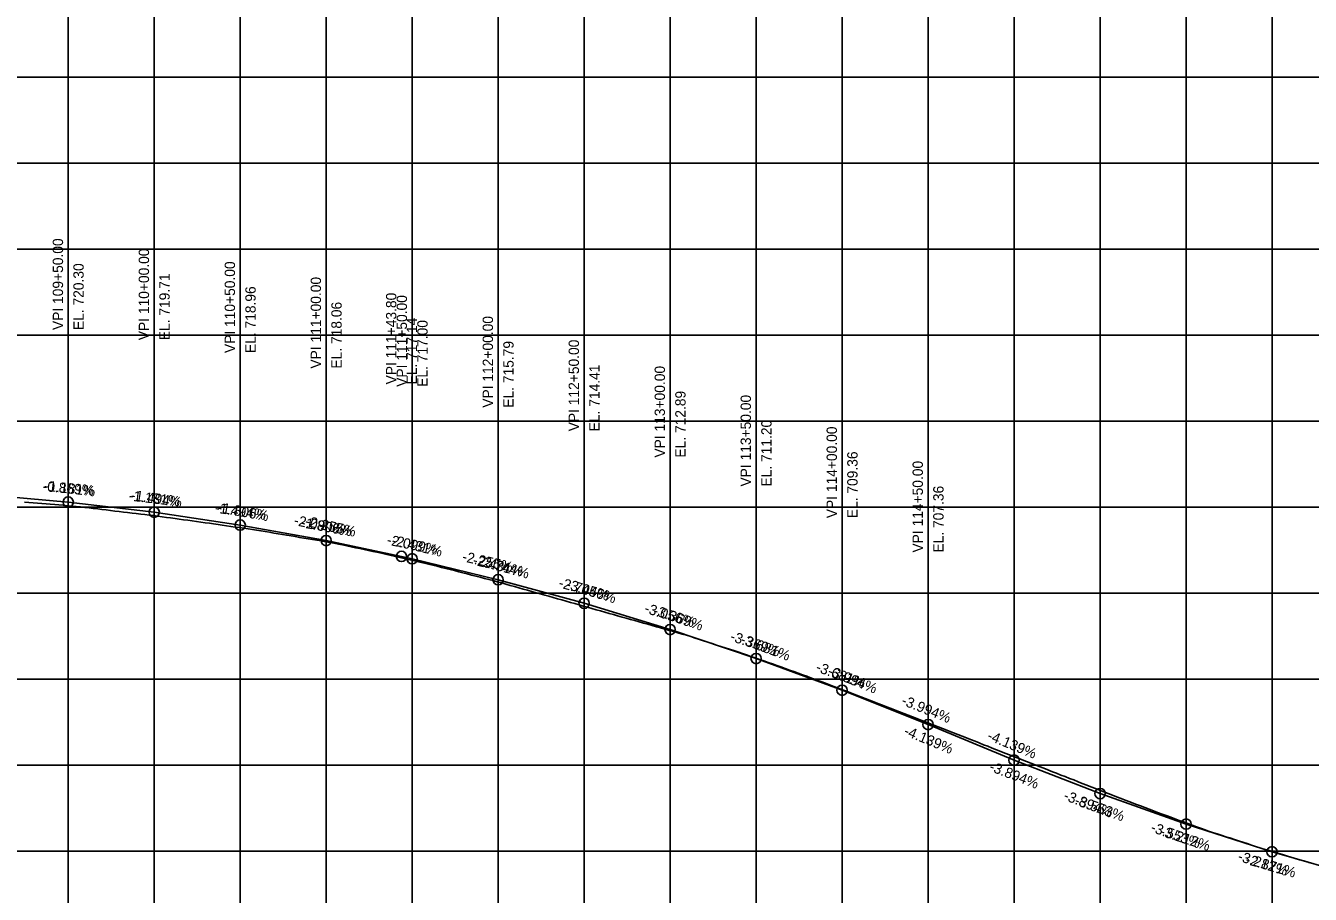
# Model space of a CAD drawing. Extents: x -7164 to 2214450, y -19642 to 253469.
# Drawn here: x 18125 to 18872, y -2525 to -2020 of the extents above; entities that cross this region are included whole.
import ezdxf

# ---------------------------------------------------------------- set-up
doc = ezdxf.new("R2010")
doc.units = 0
for name, color, linetype in [('DESIGN - PROFILE - Proposed', 7, 'Continuous'), ('DESIGN - PROFILE - Proposed Curve Text', 7, 'Continuous'), ('DESIGN - PROFILE - Proposed Text', 7, 'Continuous'), ('DESIGN - SHEET - Light Grid', 7, 'Continuous'), ('SURVEY - PROFILE - Ground Line with Text', 7, 'Continuous')]:
    doc.layers.add(name, color=color, linetype=linetype)

msp = doc.modelspace()

# ---------------------------------------------------------------- linework, layer by layer
at = {"layer": 'DESIGN - PROFILE - Proposed'}
msp.add_lwpolyline([(18100, -2292.64), (18150, -2296.98), (18200, -2302.89), (18250, -2310.36), (18300, -2319.39), (18343.8, -2328.59), (18350, -2329.98), (18400, -2342.14), (18450, -2355.86), (18500, -2371.14), (18550, -2387.98), (18600, -2406.39), (18650, -2426.36), (18700, -2447.06), (18750, -2466.53), (18800, -2484.29), (18850, -2500.35), (18900, -2514.7)], dxfattribs=at)
msp.add_lwpolyline([(18100, -2292.64), (18150, -2296.98), (18200, -2302.89), (18250, -2310.36), (18300, -2319.39), (18343.8, -2328.59), (18350, -2329.98), (18400, -2342.14), (18450, -2355.86), (18500, -2371.14), (18550, -2387.98), (18600, -2406.39), (18650, -2426.36), (18700, -2447.06), (18750, -2466.53), (18800, -2484.29), (18850, -2500.35), (18900, -2514.7)], dxfattribs=at)
at = {"layer": 'DESIGN - PROFILE - Proposed Text'}
for centre in [(18150, -2296.98), (18150, -2296.98), (18200, -2302.89), (18200, -2302.89), (18250, -2310.36), (18250, -2310.36), (18300, -2319.39), (18300, -2319.39), (18343.8, -2328.59), (18343.8, -2328.59), (18350, -2329.98), (18350, -2329.98), (18400, -2342.14), (18400, -2342.14), (18450, -2355.86), (18450, -2355.86), (18500, -2371.14), (18500, -2371.14), (18550, -2387.98), (18550, -2387.98), (18600, -2406.39), (18600, -2406.39), (18650, -2426.36), (18650, -2426.36), (18700, -2447.06), (18700, -2447.06), (18750, -2466.53), (18750, -2466.53), (18800, -2484.29), (18800, -2484.29), (18850, -2500.35), (18850, -2500.35)]:
    msp.add_circle(centre, 3, dxfattribs=at)
at = {"layer": 'DESIGN - SHEET - Light Grid'}
for p, q in [((18150, -3000), (18150, -1000)), ((18150, -3000), (18150, -1000)), ((18200, -3000), (18200, -1000)), ((18200, -3000), (18200, -1000)), ((18250, -3000), (18250, -1000)), ((18250, -3000), (18250, -1000)), ((18300, -3000), (18300, -1000)), ((18300, -3000), (18300, -1000)), ((18350, -3000), (18350, -1000)), ((18350, -3000), (18350, -1000)), ((18400, -3000), (18400, -1000)), ((18400, -3000), (18400, -1000)), ((18450, -3000), (18450, -1000)), ((18450, -3000), (18450, -1000)), ((18500, -3000), (18500, -1000)), ((18500, -3000), (18500, -1000)), ((18550, -3000), (18550, -1000)), ((18550, -3000), (18550, -1000)), ((18600, -3000), (18600, -1000)), ((18600, -3000), (18600, -1000)), ((18650, -3000), (18650, -1000)), ((18650, -3000), (18650, -1000)), ((18700, -3000), (18700, -1000)), ((18700, -3000), (18700, -1000)), ((18750, -3000), (18750, -1000)), ((18750, -3000), (18750, -1000)), ((18800, -3000), (18800, -1000)), ((18800, -3000), (18800, -1000)), ((18850, -3000), (18850, -1000)), ((18850, -3000), (18850, -1000)), ((15000, -2050), (24100, -2050)), ((15000, -2050), (24100, -2050)), ((15000, -2100), (24100, -2100)), ((15000, -2100), (24100, -2100)), ((15000, -2150), (24100, -2150)), ((15000, -2150), (24100, -2150)), ((15000, -2200), (24100, -2200)), ((15000, -2200), (24100, -2200)), ((15000, -2250), (24100, -2250)), ((15000, -2250), (24100, -2250)), ((15000, -2300), (24100, -2300)), ((15000, -2300), (24100, -2300)), ((15000, -2350), (24100, -2350)), ((15000, -2350), (24100, -2350)), ((15000, -2400), (24100, -2400)), ((15000, -2400), (24100, -2400)), ((15000, -2450), (24100, -2450)), ((15000, -2450), (24100, -2450)), ((15000, -2500), (24100, -2500)), ((15000, -2500), (24100, -2500))]:
    msp.add_line(p, q, dxfattribs=at)
at = {"layer": 'SURVEY - PROFILE - Ground Line with Text'}
for points in [[(18124.57, -2297), (18127.15, -2297.21), (18129.57, -2297.42), (18132.15, -2297.63), (18134.57, -2297.84), (18137.14, -2298.05), (18139.57, -2298.26), (18142.14, -2298.47), (18144.57, -2298.68), (18147.14, -2298.89), (18149.57, -2299.1), (18152.14, -2299.31), (18154.57, -2299.61), (18157.14, -2299.81), (18159.57, -2300.11), (18162.14, -2300.41), (18164.57, -2300.71), (18167.14, -2301.01), (18169.57, -2301.3), (18172.14, -2301.6), (18174.57, -2301.9), (18177.14, -2302.2), (18179.57, -2302.5), (18182.14, -2302.8), (18184.57, -2303.09), (18187.14, -2303.39), (18189.57, -2303.69), (18192.14, -2303.99), (18194.57, -2304.29), (18197.13, -2304.59), (18199.57, -2304.88), (18202.13, -2305.25), (18204.57, -2305.55), (18207.13, -2305.92), (18209.57, -2306.21), (18212.13, -2306.58), (18214.57, -2306.88), (18217.13, -2307.25), (18219.57, -2307.54), (18222.13, -2307.91), (18224.57, -2308.26), (18227.13, -2308.63), (18229.57, -2308.99), (18232.12, -2309.35), (18234.57, -2309.71), (18237.12, -2310.07), (18239.57, -2310.43), (18242.12, -2310.79), (18244.57, -2311.15), (18247.12, -2311.51), (18249.57, -2311.87), (18252.12, -2312.23), (18254.57, -2312.59), (18257.11, -2312.95), (18259.57, -2313.31), (18262.11, -2313.75), (18264.56, -2314.15), (18267.11, -2314.59), (18269.56, -2315), (18272.11, -2315.43), (18274.56, -2315.84), (18277.11, -2316.27), (18279.56, -2316.68), (18282.11, -2317.12), (18284.56, -2317.52)], [(18124.57, -2297), (18127.15, -2297.21), (18129.57, -2297.42), (18132.15, -2297.63), (18134.57, -2297.84), (18137.14, -2298.05), (18139.57, -2298.26), (18142.14, -2298.47), (18144.57, -2298.68), (18147.14, -2298.89), (18149.57, -2299.1), (18152.14, -2299.31), (18154.57, -2299.61), (18157.14, -2299.81), (18159.57, -2300.11), (18162.14, -2300.41), (18164.57, -2300.71), (18167.14, -2301.01), (18169.57, -2301.3), (18172.14, -2301.6), (18174.57, -2301.9), (18177.14, -2302.2), (18179.57, -2302.5), (18182.14, -2302.8), (18184.57, -2303.09), (18187.14, -2303.39), (18189.57, -2303.69), (18192.14, -2303.99), (18194.57, -2304.29), (18197.13, -2304.59), (18199.57, -2304.88), (18202.13, -2305.25), (18204.57, -2305.55), (18207.13, -2305.92), (18209.57, -2306.21), (18212.13, -2306.58), (18214.57, -2306.88), (18217.13, -2307.25), (18219.57, -2307.54), (18222.13, -2307.91), (18224.57, -2308.26), (18227.13, -2308.63), (18229.57, -2308.99), (18232.12, -2309.35), (18234.57, -2309.71), (18237.12, -2310.07), (18239.57, -2310.43), (18242.12, -2310.79), (18244.57, -2311.15), (18247.12, -2311.51), (18249.57, -2311.87), (18252.12, -2312.23), (18254.57, -2312.59), (18257.11, -2312.95), (18259.57, -2313.31), (18262.11, -2313.75), (18264.56, -2314.15), (18267.11, -2314.59), (18269.56, -2315), (18272.11, -2315.43), (18274.56, -2315.84), (18277.11, -2316.27), (18279.56, -2316.68), (18282.11, -2317.12), (18284.56, -2317.52)], [(18284.56, -2317.52), (18287.11, -2317.96), (18289.56, -2318.37), (18292.11, -2318.8), (18294.56, -2319.21), (18297.11, -2319.64), (18299.56, -2320.05), (18302.11, -2320.49), (18304.56, -2320.98), (18307.11, -2321.41), (18309.56, -2321.9), (18312.11, -2322.48), (18314.55, -2322.97), (18317.11, -2323.55), (18319.55, -2324.04), (18322.1, -2324.61), (18324.55, -2325.1), (18327.1, -2325.68), (18329.55, -2326.17), (18332.1, -2326.75), (18334.55, -2327.31), (18337.1, -2327.89), (18339.55, -2328.46), (18342.1, -2329.03), (18344.55, -2329.6), (18347.09, -2330.17), (18349.55, -2330.74), (18352.09, -2331.32), (18354.55, -2331.88), (18357.09, -2332.46), (18359.54, -2333.03), (18362.09, -2333.68), (18364.54, -2334.31), (18367.08, -2334.97), (18369.54, -2335.6), (18372.08, -2336.25), (18374.54, -2336.89), (18377.08, -2337.54), (18379.54, -2338.17), (18382.08, -2338.83), (18384.54, -2339.46), (18387.08, -2340.11), (18389.53, -2340.75), (18392.07, -2341.4), (18394.53, -2342.03), (18397.07, -2342.69), (18399.53, -2343.32), (18402.07, -2344.04), (18404.53, -2344.74), (18407.06, -2345.45), (18409.53, -2346.15), (18412.06, -2346.86), (18414.52, -2347.57), (18417.06, -2348.28), (18419.52, -2348.98), (18422.06, -2349.69), (18424.52, -2350.39), (18427.06, -2351.11), (18429.52, -2351.81), (18432.05, -2352.52), (18434.52, -2353.22), (18437.05, -2353.94), (18439.51, -2354.64), (18442.05, -2355.35), (18444.51, -2356.05), (18447.05, -2356.77), (18449.51, -2357.47), (18452.04, -2358.18), (18454.51, -2358.88), (18457.04, -2359.6), (18459.51, -2360.3), (18462.04, -2361.01), (18464.5, -2361.71), (18467.04, -2362.43), (18469.5, -2363.13), (18472.04, -2363.84), (18474.5, -2364.54), (18477.03, -2365.26), (18479.5, -2365.96), (18482.03, -2366.67), (18484.5, -2367.37), (18487.03, -2368.09), (18489.49, -2368.79), (18492.03, -2369.5), (18494.49, -2370.2), (18497.03, -2370.91), (18499.49, -2371.62), (18502.02, -2372.33), (18504.49, -2373.03), (18507.02, -2373.74), (18509.49, -2374.45), (18512.02, -2375.26), (18514.48, -2376.07), (18517.02, -2376.88), (18519.48, -2377.69), (18522.02, -2378.5), (18524.48, -2379.31), (18527.02, -2380.13), (18529.47, -2380.94), (18532.02, -2381.75), (18534.47, -2382.56)], [(18284.56, -2317.52), (18287.11, -2317.96), (18289.56, -2318.37), (18292.11, -2318.8), (18294.56, -2319.21), (18297.11, -2319.64), (18299.56, -2320.05), (18302.11, -2320.49), (18304.56, -2320.98), (18307.11, -2321.41), (18309.56, -2321.9), (18312.11, -2322.48), (18314.55, -2322.97), (18317.11, -2323.55), (18319.55, -2324.04), (18322.1, -2324.61), (18324.55, -2325.1), (18327.1, -2325.68), (18329.55, -2326.17), (18332.1, -2326.75), (18334.55, -2327.31), (18337.1, -2327.89), (18339.55, -2328.46), (18342.1, -2329.03), (18344.55, -2329.6), (18347.09, -2330.17), (18349.55, -2330.74), (18352.09, -2331.32), (18354.55, -2331.88), (18357.09, -2332.46), (18359.54, -2333.03), (18362.09, -2333.68), (18364.54, -2334.31), (18367.08, -2334.97), (18369.54, -2335.6), (18372.08, -2336.25), (18374.54, -2336.89), (18377.08, -2337.54), (18379.54, -2338.17), (18382.08, -2338.83), (18384.54, -2339.46), (18387.08, -2340.11), (18389.53, -2340.75), (18392.07, -2341.4), (18394.53, -2342.03), (18397.07, -2342.69), (18399.53, -2343.32), (18402.07, -2344.04), (18404.53, -2344.74), (18407.06, -2345.45), (18409.53, -2346.15), (18412.06, -2346.86), (18414.52, -2347.57), (18417.06, -2348.28), (18419.52, -2348.98), (18422.06, -2349.69), (18424.52, -2350.39), (18427.06, -2351.11), (18429.52, -2351.81), (18432.05, -2352.52), (18434.52, -2353.22), (18437.05, -2353.94), (18439.51, -2354.64), (18442.05, -2355.35), (18444.51, -2356.05), (18447.05, -2356.77), (18449.51, -2357.47), (18452.04, -2358.18), (18454.51, -2358.88), (18457.04, -2359.6), (18459.51, -2360.3), (18462.04, -2361.01), (18464.5, -2361.71), (18467.04, -2362.43), (18469.5, -2363.13), (18472.04, -2363.84), (18474.5, -2364.54), (18477.03, -2365.26), (18479.5, -2365.96), (18482.03, -2366.67), (18484.5, -2367.37), (18487.03, -2368.09), (18489.49, -2368.79), (18492.03, -2369.5), (18494.49, -2370.2), (18497.03, -2370.91), (18499.49, -2371.62), (18502.02, -2372.33), (18504.49, -2373.03), (18507.02, -2373.74), (18509.49, -2374.45), (18512.02, -2375.26), (18514.48, -2376.07), (18517.02, -2376.88), (18519.48, -2377.69), (18522.02, -2378.5), (18524.48, -2379.31), (18527.02, -2380.13), (18529.47, -2380.94), (18532.02, -2381.75), (18534.47, -2382.56)], [(18534.47, -2382.56), (18537.02, -2383.37), (18539.47, -2384.18), (18542.01, -2385.1), (18544.46, -2385.91), (18547.01, -2386.82), (18549.46, -2387.63), (18552.01, -2388.55), (18554.46, -2389.36), (18557.01, -2390.28), (18559.45, -2391.08), (18562.01, -2392), (18564.45, -2392.89), (18567, -2393.81), (18569.45, -2394.7), (18572, -2395.62), (18574.44, -2396.51), (18577, -2397.44), (18579.44, -2398.32), (18580.31, -2398.66), (18582.74, -2399.54), (18585.3, -2400.52), (18587.74, -2401.41), (18590.3, -2402.39), (18592.73, -2403.27), (18595.3, -2404.26), (18597.72, -2405.14), (18600.29, -2406.12), (18600.89, -2406.36), (18603.46, -2407.35), (18605.89, -2408.3), (18608.46, -2409.29), (18610.88, -2410.24), (18613.46, -2411.23), (18613.52, -2411.25), (18615.88, -2412.18), (18618.46, -2413.17), (18620.87, -2414.12), (18623.46, -2415.11), (18625.87, -2416.07), (18628.46, -2417.06), (18630.87, -2418.01), (18633.45, -2419), (18635.86, -2419.95), (18638.45, -2420.94), (18640.86, -2421.89), (18643.45, -2422.88), (18645.85, -2423.83), (18648.45, -2424.82), (18650.85, -2425.77), (18653.45, -2426.76), (18655.85, -2427.71), (18658.45, -2428.71), (18660.84, -2429.65), (18662.35, -2430.24), (18664.74, -2431.18), (18667.34, -2432.2), (18669.74, -2433.14), (18672.34, -2434.16), (18674.73, -2435.11), (18677.34, -2436.12), (18679.73, -2437.07), (18682.33, -2438.09), (18684.72, -2439.03), (18687.33, -2440.05), (18689.72, -2440.99), (18692.33, -2442.01), (18694.71, -2442.95), (18697.32, -2443.97), (18699.71, -2444.91), (18702.32, -2445.93), (18704.7, -2446.87), (18707.32, -2447.89), (18709.7, -2448.83), (18712.31, -2449.86), (18714.69, -2450.8), (18717.31, -2451.82), (18719.69, -2452.76), (18722.31, -2453.78), (18724.69, -2454.71), (18727.3, -2455.73), (18729.68, -2456.66), (18732.3, -2457.68), (18734.68, -2458.61), (18737.29, -2459.63), (18739.68, -2460.56), (18742.29, -2461.58), (18744.67, -2462.51), (18747.29, -2463.53), (18749.67, -2464.46), (18752.28, -2465.48), (18754.67, -2466.41), (18757.28, -2467.43), (18759.66, -2468.36), (18762.27, -2469.37), (18764.66, -2470.31), (18767.27, -2471.32), (18769.66, -2472.25), (18771.12, -2472.8), (18773.51, -2473.73), (18776.12, -2474.7)], [(18534.47, -2382.56), (18537.02, -2383.37), (18539.47, -2384.18), (18542.01, -2385.1), (18544.46, -2385.91), (18547.01, -2386.82), (18549.46, -2387.63), (18552.01, -2388.55), (18554.46, -2389.36), (18557.01, -2390.28), (18559.45, -2391.08), (18562.01, -2392), (18564.45, -2392.89), (18567, -2393.81), (18569.45, -2394.7), (18572, -2395.62), (18574.44, -2396.51), (18577, -2397.44), (18579.44, -2398.32), (18580.31, -2398.66), (18582.74, -2399.54), (18585.3, -2400.52), (18587.74, -2401.41), (18590.3, -2402.39), (18592.73, -2403.27), (18595.3, -2404.26), (18597.72, -2405.14), (18600.29, -2406.12), (18600.89, -2406.36), (18603.46, -2407.35), (18605.89, -2408.3), (18608.46, -2409.29), (18610.88, -2410.24), (18613.46, -2411.23), (18613.52, -2411.25), (18615.88, -2412.18), (18618.46, -2413.17), (18620.87, -2414.12), (18623.46, -2415.11), (18625.87, -2416.07), (18628.46, -2417.06), (18630.87, -2418.01), (18633.45, -2419), (18635.86, -2419.95), (18638.45, -2420.94), (18640.86, -2421.89), (18643.45, -2422.88), (18645.85, -2423.83), (18648.45, -2424.82), (18650.85, -2425.77), (18653.45, -2426.76), (18655.85, -2427.71), (18658.45, -2428.71), (18660.84, -2429.65), (18662.35, -2430.24), (18664.74, -2431.18), (18667.34, -2432.2), (18669.74, -2433.14), (18672.34, -2434.16), (18674.73, -2435.11), (18677.34, -2436.12), (18679.73, -2437.07), (18682.33, -2438.09), (18684.72, -2439.03), (18687.33, -2440.05), (18689.72, -2440.99), (18692.33, -2442.01), (18694.71, -2442.95), (18697.32, -2443.97), (18699.71, -2444.91), (18702.32, -2445.93), (18704.7, -2446.87), (18707.32, -2447.89), (18709.7, -2448.83), (18712.31, -2449.86), (18714.69, -2450.8), (18717.31, -2451.82), (18719.69, -2452.76), (18722.31, -2453.78), (18724.69, -2454.71), (18727.3, -2455.73), (18729.68, -2456.66), (18732.3, -2457.68), (18734.68, -2458.61), (18737.29, -2459.63), (18739.68, -2460.56), (18742.29, -2461.58), (18744.67, -2462.51), (18747.29, -2463.53), (18749.67, -2464.46), (18752.28, -2465.48), (18754.67, -2466.41), (18757.28, -2467.43), (18759.66, -2468.36), (18762.27, -2469.37), (18764.66, -2470.31), (18767.27, -2471.32), (18769.66, -2472.25), (18771.12, -2472.8), (18773.51, -2473.73), (18776.12, -2474.7)], [(18776.12, -2474.7), (18778.51, -2475.64), (18781.11, -2476.61), (18783.5, -2477.47), (18786.11, -2478.45), (18788.5, -2479.31), (18791.11, -2480.29), (18793.49, -2481.15), (18796.1, -2482.12), (18798.49, -2482.99), (18801.1, -2483.96), (18803.48, -2484.83), (18806.1, -2485.8), (18808.48, -2486.66), (18811.09, -2487.64), (18813.1, -2488.31), (18815.49, -2489.07), (18818.1, -2489.94), (18820.48, -2490.7), (18823.1, -2491.58), (18825.48, -2492.34), (18828.1, -2493.21), (18830.48, -2493.97), (18833.1, -2494.84), (18835.47, -2495.6), (18838.09, -2496.48), (18840.47, -2497.23), (18841.05, -2497.4), (18843.42, -2498.16), (18846.05, -2498.94), (18848.42, -2499.7), (18851.04, -2500.48), (18853.42, -2501.23), (18856.04, -2502.01), (18858.41, -2502.77), (18861.04, -2503.55), (18863.42, -2504.22), (18866.04, -2505.01), (18868.42, -2505.68), (18871.03, -2506.46), (18871.22, -2506.51), (18873.6, -2507.19)], [(18776.12, -2474.7), (18778.51, -2475.64), (18781.11, -2476.61), (18783.5, -2477.47), (18786.11, -2478.45), (18788.5, -2479.31), (18791.11, -2480.29), (18793.49, -2481.15), (18796.1, -2482.12), (18798.49, -2482.99), (18801.1, -2483.96), (18803.48, -2484.83), (18806.1, -2485.8), (18808.48, -2486.66), (18811.09, -2487.64), (18813.1, -2488.31), (18815.49, -2489.07), (18818.1, -2489.94), (18820.48, -2490.7), (18823.1, -2491.58), (18825.48, -2492.34), (18828.1, -2493.21), (18830.48, -2493.97), (18833.1, -2494.84), (18835.47, -2495.6), (18838.09, -2496.48), (18840.47, -2497.23), (18841.05, -2497.4), (18843.42, -2498.16), (18846.05, -2498.94), (18848.42, -2499.7), (18851.04, -2500.48), (18853.42, -2501.23), (18856.04, -2502.01), (18858.41, -2502.77), (18861.04, -2503.55), (18863.42, -2504.22), (18866.04, -2505.01), (18868.42, -2505.68), (18871.03, -2506.46), (18871.22, -2506.51), (18873.6, -2507.19)]]:
    msp.add_lwpolyline(points, dxfattribs=at)

# ---------------------------------------------------------------- texts
at = {"layer": 'DESIGN - PROFILE - Proposed Curve Text'}
for s, p in [('VPI 109+50.00', (18147, -2196.98)), ('VPI 109+50.00', (18147, -2196.98)), ('VPI 110+00.00', (18197, -2202.89)), ('VPI 110+00.00', (18197, -2202.89)), ('EL. 720.30', (18159, -2196.98)), ('EL. 720.30', (18159, -2196.98)), ('VPI 110+50.00', (18247, -2210.36)), ('VPI 110+50.00', (18247, -2210.36)), ('EL. 719.71', (18209, -2202.89)), ('EL. 719.71', (18209, -2202.89)), ('EL. 718.96', (18259, -2210.36)), ('EL. 718.96', (18259, -2210.36)), ('VPI 111+00.00', (18297, -2219.39)), ('VPI 111+00.00', (18297, -2219.39)), ('EL. 718.06', (18309, -2219.39)), ('EL. 718.06', (18309, -2219.39)), ('VPI 111+43.80', (18340.8, -2228.59)), ('VPI 111+43.80', (18340.8, -2228.59)), ('VPI 111+50.00', (18347, -2229.98)), ('VPI 111+50.00', (18347, -2229.98)), ('EL. 717.14', (18352.8, -2228.59)), ('EL. 717.14', (18352.8, -2228.59)), ('EL. 717.00', (18359, -2229.98)), ('EL. 717.00', (18359, -2229.98)), ('VPI 112+00.00', (18397, -2242.14)), ('VPI 112+00.00', (18397, -2242.14)), ('VPI 112+50.00', (18447, -2255.86)), ('VPI 112+50.00', (18447, -2255.86)), ('EL. 715.79', (18409, -2242.14)), ('EL. 715.79', (18409, -2242.14)), ('EL. 714.41', (18459, -2255.86)), ('EL. 714.41', (18459, -2255.86)), ('VPI 113+00.00', (18497, -2271.14)), ('VPI 113+00.00', (18497, -2271.14)), ('EL. 712.89', (18509, -2271.14)), ('EL. 712.89', (18509, -2271.14)), ('VPI 113+50.00', (18547, -2287.98)), ('VPI 113+50.00', (18547, -2287.98)), ('EL. 711.20', (18559, -2287.98)), ('EL. 711.20', (18559, -2287.98)), ('VPI 114+00.00', (18597, -2306.39)), ('VPI 114+00.00', (18597, -2306.39)), ('EL. 709.36', (18609, -2306.39)), ('EL. 709.36', (18609, -2306.39)), ('VPI 114+50.00', (18647, -2326.36)), ('VPI 114+50.00', (18647, -2326.36)), ('EL. 707.36', (18659, -2326.36)), ('EL. 707.36', (18659, -2326.36))]:
    msp.add_text(s, height=6, rotation=90, dxfattribs=at).set_placement(p)
at = {"layer": 'DESIGN - PROFILE - Proposed Text'}
for s, rotation, p in [('-0.869%', 355.03575, (18134.96, -2290.66)), ('-0.869%', 355.03575, (18134.96, -2290.66)), ('-1.181%', 353.26231, (18135.7, -2290.26)), ('-1.181%', 353.26231, (18135.7, -2290.26)), ('-1.181%', 353.26231, (18185.01, -2296.08)), ('-1.181%', 353.26231, (18185.01, -2296.08)), ('-1.494%', 351.5051, (18186.11, -2295.76)), ('-1.494%', 351.5051, (18186.11, -2295.76)), ('-1.494%', 351.5051, (18235.02, -2303.07)), ('-1.494%', 351.5051, (18235.02, -2303.07)), ('-1.806%', 349.76051, (18236.59, -2302.85)), ('-1.806%', 349.76051, (18236.59, -2302.85)), ('-2.099%', 348.14398, (18280.88, -2310.27)), ('-2.099%', 348.14398, (18280.88, -2310.27)), ('-1.806%', 349.76051, (18285, -2311.6)), ('-1.806%', 349.76051, (18285, -2311.6)), ('-2.255%', 347.29323, (18287.36, -2310.73)), ('-2.255%', 347.29323, (18287.36, -2310.73)), ('-2.099%', 348.14398, (18334.95, -2321.62)), ('-2.099%', 348.14398, (18334.95, -2321.62)), ('-2.431%', 346.33428, (18337.69, -2321.84)), ('-2.431%', 346.33428, (18337.69, -2321.84)), ('-2.255%', 347.29323, (18378.71, -2331.33)), ('-2.255%', 347.29323, (18378.71, -2331.33)), ('-2.431%', 346.33428, (18384.86, -2333.31)), ('-2.431%', 346.33428, (18384.86, -2333.31)), ('-2.744%', 344.65785, (18388.31, -2333.75)), ('-2.744%', 344.65785, (18388.31, -2333.75)), ('-2.744%', 344.65785, (18434.75, -2346.49)), ('-2.744%', 344.65785, (18434.75, -2346.49)), ('-3.056%', 343.00475, (18438.97, -2347.26)), ('-3.056%', 343.00475, (18438.97, -2347.26)), ('-3.056%', 343.00475, (18484.61, -2361.21)), ('-3.056%', 343.00475, (18484.61, -2361.21)), ('-3.369%', 341.38339, (18489.67, -2362.39)), ('-3.369%', 341.38339, (18489.67, -2362.39)), ('-3.369%', 341.38339, (18534.44, -2377.47)), ('-3.369%', 341.38339, (18534.44, -2377.47)), ('-3.681%', 339.78932, (18540.41, -2379.12)), ('-3.681%', 339.78932, (18540.41, -2379.12)), ('-3.681%', 339.78932, (18584.25, -2395.26)), ('-3.681%', 339.78932, (18584.25, -2395.26)), ('-3.994%', 338.23021, (18591.17, -2397.48)), ('-3.994%', 338.23021, (18591.17, -2397.48)), ('-3.994%', 338.23021, (18634.04, -2414.6)), ('-3.994%', 338.23021, (18634.04, -2414.6)), ('-4.139%', 337.51338, (18635.42, -2432.23)), ('-4.139%', 337.51338, (18635.42, -2432.23)), ('-4.139%', 337.51338, (18683.94, -2434.99)), ('-4.139%', 337.51338, (18683.94, -2434.99)), ('-3.894%', 338.72307, (18685.12, -2453.06)), ('-3.894%', 338.72307, (18685.12, -2453.06)), ('-3.894%', 338.72307, (18728.3, -2469.88)), ('-3.894%', 338.72307, (18728.3, -2469.88)), ('-3.553%', 340.44089, (18734.75, -2472.78)), ('-3.553%', 340.44089, (18734.75, -2472.78)), ('-3.553%', 340.44089, (18778.98, -2488.49)), ('-3.553%', 340.44089, (18778.98, -2488.49)), ('-3.212%', 342.19402, (18784.43, -2490.84)), ('-3.212%', 342.19402, (18784.43, -2490.84)), ('-3.212%', 342.19402, (18829.63, -2505.36)), ('-3.212%', 342.19402, (18829.63, -2505.36)), ('-2.871%', 343.98334, (18834.16, -2507.25)), ('-2.871%', 343.98334, (18834.16, -2507.25))]:
    msp.add_text(s, height=6, rotation=rotation, dxfattribs=at).set_placement(p)

doc.saveas('drawing.dxf')
